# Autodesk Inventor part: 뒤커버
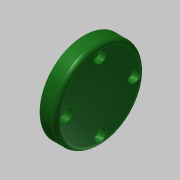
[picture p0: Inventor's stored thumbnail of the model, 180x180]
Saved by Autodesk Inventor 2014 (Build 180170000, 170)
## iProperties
Created: 2015-11
Part Number: 뒤커버
Material: 알루미늄 6061
Document SubType Name: Modeling
Designer: mduedu
Density: 1 g/cm^3
Appearance: Smooth - Dark Forest Green
Author: mduedu
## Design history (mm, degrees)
sketch "스케치5"
  geometry: C1 r 30 at (0, 0); 2 further points
  constraints: 2 coincident, 1 centre point
  dimensions: "d66" = 60 diameter of C1
extrude "돌출2" new body sketch "스케치5" distance "d67" = 11; taper "d68" = 0 deg
sketch "스케치6"
  geometry: C1 r 16 at (0, 0); 1 further point
  constraints: 1 centre point, 1 coincident
  dimensions: "d69" = 32 diameter of C1
extrude "돌출3" join sketch "스케치6" distance "d70" = 3; taper "d71" = 0 deg
hole "구멍5" diameter "d74" = 25; stored, may be unused: countersink angle "d78" = 90 deg, drill point angle "d80" = 0 deg; dims "d72" = 10, "d73" = 10, "d75" = 6, "d76" = 4, "d77" = 2, "d79" = 10
fillet "모깎기8" dims "d82" = 3
fillet "모깎기9" dims "d83" = 3
fillet "모깎기10" dims "d84" = 0.3
sketch "스케치7" dims "d85" = 46
  geometry: 3 further points
  constraints: 2 vertical alignment, 1 coincident, 2 other
hole "구멍6" sketch "스케치7" at (0, 23) diameter "d86" = 4.5; stored, may be unused: countersink angle "d90" = 90 deg, drill point angle "d92" = 0 deg; dims "d87" = 6, "d88" = 8, "d89" = 4.6, "d91" = 10
node "솔리드2"
pattern_circular "원형 패턴3" dims angle "d94" = 360 deg
